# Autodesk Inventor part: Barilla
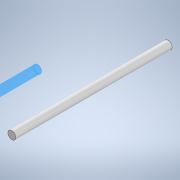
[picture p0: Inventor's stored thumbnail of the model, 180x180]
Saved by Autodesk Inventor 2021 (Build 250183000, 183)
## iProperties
Created: 2021-02
Part Number: Barilla
Material: Genérico
Document SubType Name: Modeling
Designer: ATOUZA
Density: 1 g/cm^3
Appearance: Valor por defecto
Author: ATOUZA
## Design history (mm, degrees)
sketch "Boceto1"
  geometry: C1 r 2.5 at (0, 0); 1 further point
  constraints: 1 centre point, 1 coincident
  dimensions: "d0" = 5 diameter of C1
extrude "Extrusión1" new body sketch "Boceto1" distance "d1" = 98; taper "d2" = 0 deg
sketch "Boceto2"
  geometry: C1 r 4 at (0, 0); 1 further point
  constraints: 1 centre point, 1 coincident
  dimensions: "d3" = 8 diameter of C1
extrude "Extrusión2" join sketch "Boceto2" distance "d4" = 5; taper "d5" = 0 deg
sketch "Boceto3"
  geometry: C1 r 5 at (0, 0); 1 further point
  constraints: 1 centre point, 1 coincident
  dimensions: "d6" = 10 diameter of C1
extrude "Extrusión3" join sketch "Boceto3" distance "d7" = 8; taper "d8" = 0 deg
sketch "Boceto4"
  geometry: L1 (-2.887, -5)-(-5.774, 0); L2 (-5.774, 0)-(-2.887, 5); L3 (-2.887, 5)-(2.887, 5); L4 (2.887, 5)-(5.774, 0); L5 (5.774, 0)-(2.887, -5); L6 (2.887, -5)-(-2.887, -5); L7 (5, 0)-(-4.981, 0); 3 further points
  constraints: 14 end point, 1 coincident, 1 horizontal, 1 horizontal alignment, 1 parallel, 14 other
  dimensions: "d9" = 10 distance between parallel lines of L3 L6
extrude "Extrusión4" join sketch "Boceto4" distance "d10" = 12; taper "d11" = 0 deg
node "Plano de trabajo1"
sketch "Boceto5"
  geometry: C1 r 5 at (0, 0); 2 further points
  constraints: 1 centre point, 1 coincident
sketch "Boceto6"
  geometry: C1 r 4 at (0, 0); 1 further point
  constraints: 1 centre point, 1 coincident
  dimensions: "d13" = 8 diameter of C1
feature "Solevación1" sketch "Boceto5", "Boceto6" dims "d14" = 0, "d15" = 90 deg, "d16" = 0, "d17" = 90 deg
sketch "Boceto7"
  geometry: L1 (-0.25, -5)-(-0.25, -4.711); L2 (-0.25, -4.711)-(0.25, -4.711); L3 (0.25, -4.711)-(0.25, -5); L4 (-2.887, -5)-(2.887, -5) reference; L5 (0.25, -5.289)-(-0.25, -4.711); L6 (-0.25, -5.289)-(0.25, -4.711); L7 (0.984, -4.613)-(1.029, -4.899); L8 (0.49, -4.692)-(0.984, -4.613); L9 (0.535, -4.978)-(0.49, -4.692); L10 (1.693, -4.403)-(1.783, -4.678); L11 (1.218, -4.557)-(1.693, -4.403); L12 (1.307, -4.833)-(1.218, -4.557); L13 (2.361, -4.084)-(2.493, -4.342); L14 (1.916, -4.311)-(2.361, -4.084); L15 (2.047, -4.569)-(1.916, -4.311); L16 (2.971, -3.664)-(3.141, -3.898); L17 (2.567, -3.958)-(2.971, -3.664); L18 (2.737, -4.192)-(2.567, -3.958); L19 (3.508, -3.154)-(3.712, -3.359); L20 (3.154, -3.508)-(3.508, -3.154); L21 (3.359, -3.712)-(3.154, -3.508); L22 (3.958, -2.567)-(4.192, -2.737); L23 (3.664, -2.971)-(3.958, -2.567); L24 (3.898, -3.141)-(3.664, -2.971); L25 (4.311, -1.916)-(4.569, -2.047); L26 (4.084, -2.361)-(4.311, -1.916); L27 (4.342, -2.493)-(4.084, -2.361); L28 (4.557, -1.218)-(4.833, -1.307); L29 (4.403, -1.693)-(4.557, -1.218); L30 (4.678, -1.783)-(4.403, -1.693); L31 (4.692, -0.49)-(4.978, -0.535); L32 (4.613, -0.984)-(4.692, -0.49); L33 (4.899, -1.029)-(4.613, -0.984); L34 (4.711, 0.25)-(5, 0.25); L35 (4.711, -0.25)-(4.711, 0.25); L36 (5, -0.25)-(4.711, -0.25); L37 (4.613, 0.984)-(4.899, 1.029); L38 (4.692, 0.49)-(4.613, 0.984); L39 (4.978, 0.535)-(4.692, 0.49); L40 (4.403, 1.693)-(4.678, 1.783); L41 (4.557, 1.218)-(4.403, 1.693); L42 (4.833, 1.307)-(4.557, 1.218); L43 (4.084, 2.361)-(4.342, 2.493); L44 (4.311, 1.916)-(4.084, 2.361); L45 (4.569, 2.047)-(4.311, 1.916); L46 (3.664, 2.971)-(3.898, 3.141); L47 (3.958, 2.567)-(3.664, 2.971); L48 (4.192, 2.737)-(3.958, 2.567); L49 (3.154, 3.508)-(3.359, 3.712); L50 (3.508, 3.154)-(3.154, 3.508); L51 (3.712, 3.359)-(3.508, 3.154); L52 (2.567, 3.958)-(2.737, 4.192); L53 (2.971, 3.664)-(2.567, 3.958); L54 (3.141, 3.898)-(2.971, 3.664); L55 (1.916, 4.311)-(2.047, 4.569); L56 (2.361, 4.084)-(1.916, 4.311); L57 (2.493, 4.342)-(2.361, 4.084); L58 (1.218, 4.557)-(1.307, 4.833); L59 (1.693, 4.403)-(1.218, 4.557); L60 (1.783, 4.678)-(1.693, 4.403); L61 (0.49, 4.692)-(0.535, 4.978); L62 (0.984, 4.613)-(0.49, 4.692); L63 (1.029, 4.899)-(0.984, 4.613); L64 (-0.25, 4.711)-(-0.25, 5)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; 83 further points
  constraints: 244 end point, 81 point on line, 3 midpoint, 1 parallel, 402 other
  dimensions: "d20" = 0.5 distance of L1.end L2.end; "d23" = 360 deg dimension on point (0, 0) L2.end (derived)
extrude "Extrusión5" join sketch "Boceto7" distance "d25" = 2.3; taper "d26" = 0 deg
sketch "Boceto8"
  geometry: C1 r 5 at (0, 0); 1 further point
  constraints: 1 centre point, 1 coincident
  dimensions: "d27" = 10 diameter of C1
extrude "Extrusión6" join sketch "Boceto8" distance "d28" = 4.2; taper "d29" = 0 deg
sketch "Boceto9"
  geometry: C1 r 4.5 at (0, 0); 1 further point
  constraints: 1 centre point, 1 coincident
  dimensions: "d30" = 9 diameter of C1
extrude "Extrusión7" join sketch "Boceto9" distance "d31" = 4.2; taper "d32" = 0 deg
sketch "Boceto10"
  geometry: L1 (3.742, 2.5)-(-3.742, 2.5); L2 (-3.742, -2.5)-(3.742, -2.5); L3 (3.742, 2.5)-(-3.742, -2.5); L4 (-3.742, 2.5)-(3.742, -2.5); A1 r 4.5 centre (0, 0) between (-3.742, -2.5) and (3.742, -2.5); A2 r 4.5 centre (0, 0) between (3.742, 2.5) and (-3.742, 2.5); 2 further points
  constraints: 8 end point, 4 point on circle, 2 centre point, 2 coincident, 2 midpoint, 1 horizontal, 1 parallel
extrude "Extrusión8" join sketch "Boceto10" distance "d34" = 8.2; taper "d35" = 0 deg
sketch "Boceto11"
  geometry: L1 (0, -8.2)-(7.483, -8.2) reference; C1 r 1.25 at (3.742, -5.2); 1 further point
  constraints: 1 centre point
  dimensions: "d36" = 2.5 diameter of C1; "d37" = 3 distance from line of C1.centre L1
extrude "Extrusión9" cut sketch "Boceto11" distance "d38" = 8.2; taper "d40" = 0 deg; dims "d39" = 4.1, "d41" = 0
node "Plano de trabajo2"
sketch "Boceto12"
  geometry: C1 r 5 at (3.742, -5.078); 1 further point
  constraints: 1 centre point
  dimensions: "d42" = 10 diameter of C1
extrude "Extrusión10" join sketch "Boceto12" stored distance "d43" = 4; taper "d44" = 0 deg
node "Sólido1"
other parameters: "d12" = 5.5
